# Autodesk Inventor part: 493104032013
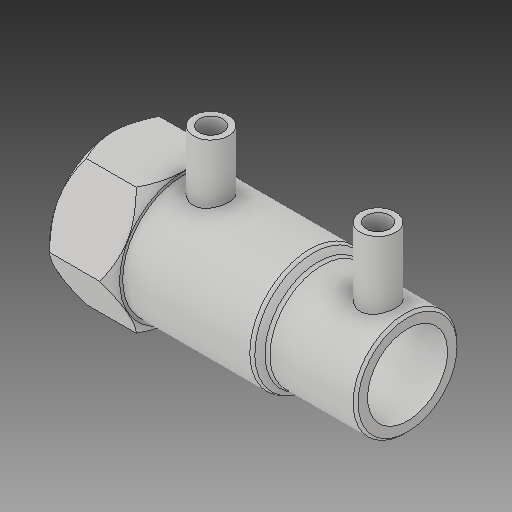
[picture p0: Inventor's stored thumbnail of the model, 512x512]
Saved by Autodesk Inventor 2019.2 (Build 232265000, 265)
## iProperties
Created: 2021-03
Part Number: 493104032013
Material: Generic
Description: Plasson Female Transition Reducer 32 x 1¼"
Document SubType Name: Modeling
Designer: Lenora
Categories: <MemberInstance><Categories><Category DisplayName="" InternalName="4347fa0f-2144-441d-94cd-e3e15c92b736" Mnemonic="TUBEANDPIPE"><CategoryParameter DisplayName="
Density: 1 g/cm^3
Appearance: Default
Author: Lenora
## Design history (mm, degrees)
derived "493104-R.ipt"
feature "Solid1::493104-R.ipt"
tag "TaggingFeature1"
body "Solid1"
other parameters: "d0" = 118, "d1" = 38.952, "d2" = 32, "d3" = 39, "d4" = 28, "d5" = 29, "d6" = 22.4, "d7" = 58.428, "d8" = 41.6, "d9" = 48, "d10" = 45 deg, "d11" = 35.1, "d12" = 39.33333, "d13" = 47, "d14" = 14.16, "d15" = 9.44, "d16" = 1, "d17" = 14.1, "d18" = 1, "d19" = 14.1, "d20" = 9.44, "d21" = 14.16, "d22" = 47, "d23" = 11.8, "d28" = 0, "d30" = 0, "d31" = 4, "d35" = 0, "d36" = 2, "d37" = 1, "d" = 32, "Rp" = 38.952, "L" = 118, "L1" = 39, "L2" = 28, "D" = 29, "A_" = 47
